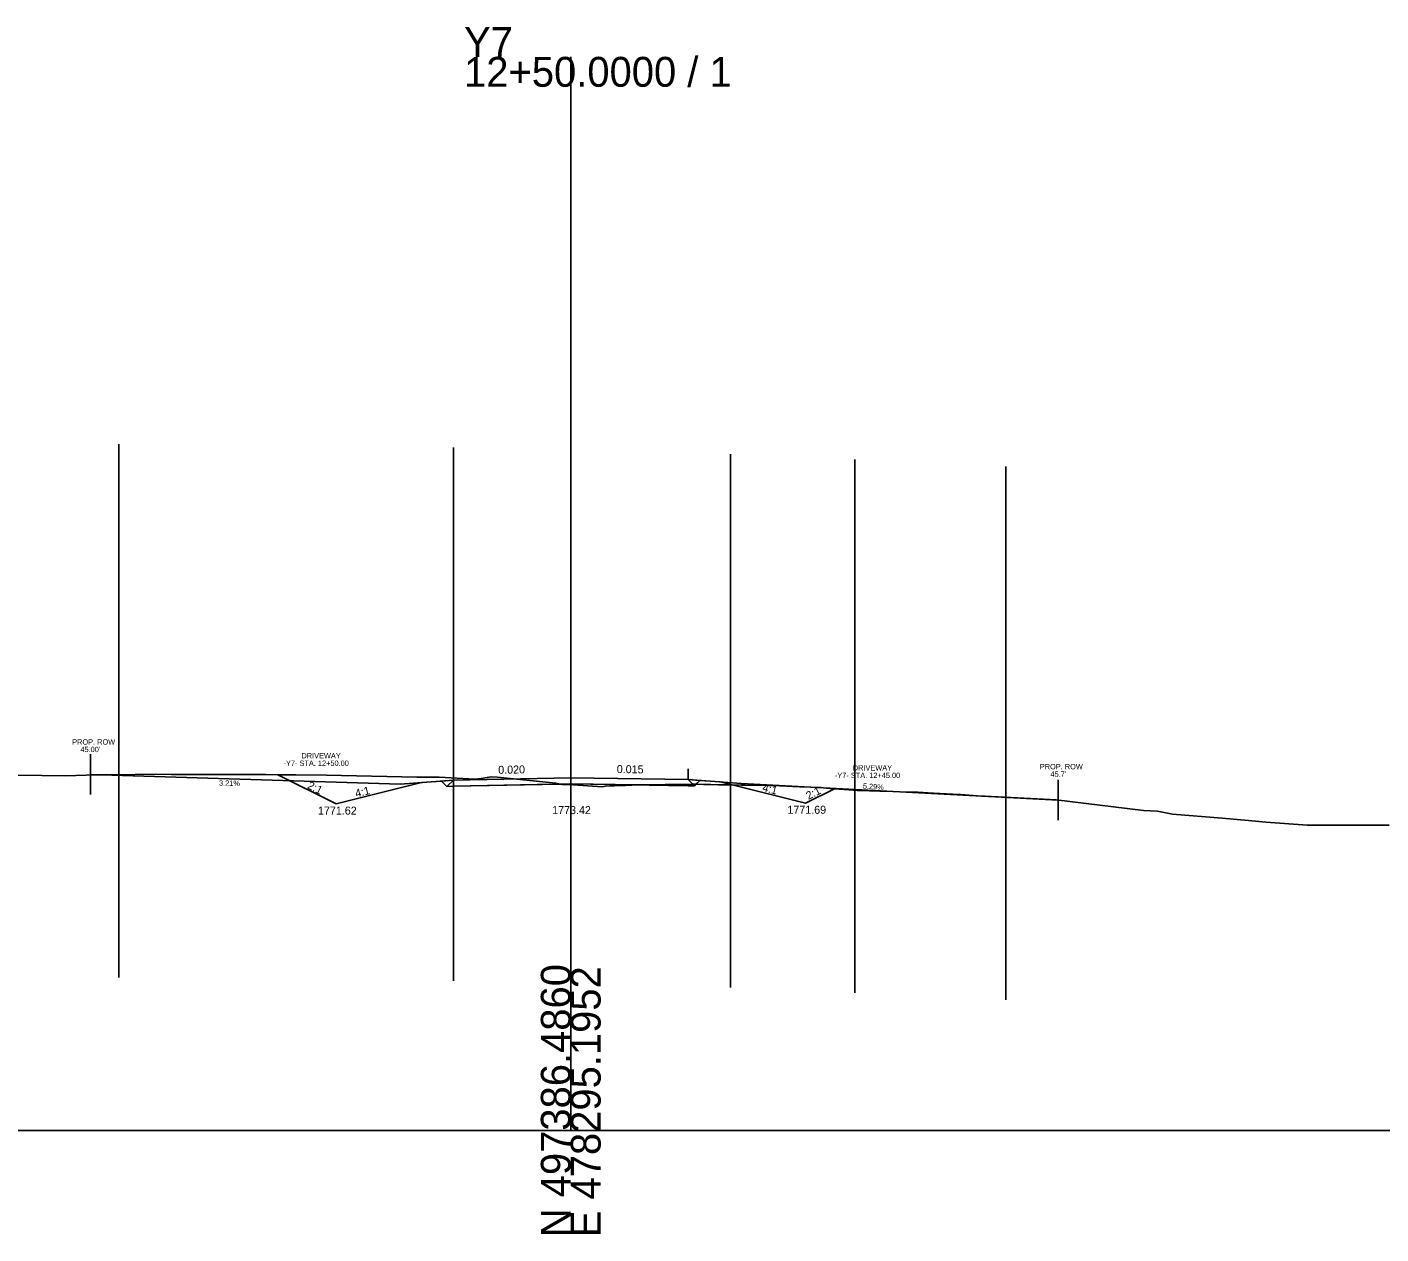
# Model space of a CAD drawing. Extents: x -26 to 403, y -10 to 4071.
# Drawn here: x 149 to 275.9, y 2490.3 to 2603.5 of the extents above; entities that cross this region are included whole.
import ezdxf

# ---------------------------------------------------------------- set-up
doc = ezdxf.new("R2010")
doc.units = 0
for name, color, linetype in [('Exist Cross Section Cell', 7, 'Continuous'), ('Exist XS Center Line Elevation Label', 7, 'Continuous'), ('Exist XS Ground Line', 7, 'Continuous'), ('Prop Road Sect_ Boring - Header (ID Tx)', 7, 'Continuous'), ('Prop Road Sect_ Boring - Material (Outline)', 7, 'Continuous'), ('Prop XS Ditch Slope Text', 7, 'Continuous'), ('Prop XS Ditch Standard Text', 7, 'Continuous'), ('Prop XS Dump Level', 7, 'Continuous'), ('Prop XS Earthwork Shape', 7, 'Continuous'), ('Prop XS EOT Tick Mark', 7, 'Continuous'), ('Prop XS Finish Grade', 7, 'Continuous'), ('Prop XS Finish Grade Earthwork', 7, 'Continuous'), ('Prop XS Finish Grade Pavement', 7, 'Continuous'), ('Prop XS Pvmt Edge Slope', 7, 'Continuous'), ('Prop XS SE Text', 7, 'Continuous'), ('Prop XS Side Slope Text', 7, 'Continuous'), ('Prop XS Subgrade Earthwork', 7, 'Continuous'), ('Scratch_Level_2', 7, 'Continuous'), ('Scratch_Level_5', 7, 'Continuous')]:
    doc.layers.add(name, color=color, linetype=linetype)

msp = doc.modelspace()

# ---------------------------------------------------------------- linework, layer by layer
at = {"layer": 'Exist Cross Section Cell'}
for p, q in [((200, 2500), (200, 2600.66)), ((0, 2500), (200, 2500)), ((200, 2500), (400, 2500))]:
    msp.add_line(p, q, dxfattribs=at)
at = {"layer": 'Exist XS Ground Line'}
msp.add_lwpolyline([(132.59, 2533.55), (152.64, 2533.26), (155.54, 2533.36), (157.27, 2533.34), (161.05, 2533.41), (162.58, 2533.39), (168.64, 2533.38), (171.39, 2533.37), (177.12, 2533.31), (185.56, 2533.13), (187.66, 2533.12), (191, 2532.93), (191.6, 2533), (192.53, 2533.16), (193.1, 2533.14), (198.59, 2532.56), (199.2, 2532.44), (200.27, 2532.41), (202.94, 2532.21), (203.25, 2532.29), (204.08, 2532.32), (205.1, 2532.34), (206.36, 2532.41), (207.76, 2532.42), (208.86, 2532.45), (210.56, 2532.45), (211.37, 2532.46), (212.45, 2532.45), (213.14, 2532.43), (213.84, 2532.42), (216, 2532.39), (216.39, 2532.39), (218.41, 2532.36), (218.97, 2532.34), (221.43, 2532.23), (223.48, 2532.16), (223.93, 2532.1), (224.29, 2532.08), (226.06, 2531.95), (226.85, 2531.89), (227.99, 2531.86), (228.97, 2531.83), (230.19, 2531.78), (231.49, 2531.74), (232.54, 2531.71), (234.01, 2531.64), (235.81, 2531.54), (236.52, 2531.51), (238.51, 2531.36), (238.85, 2531.34), (244.3, 2531.07), (245.51, 2530.99), (253.68, 2530.01), (254.99, 2529.93), (256.4, 2529.67), (261.05, 2529.29), (263.54, 2529.06), (265.15, 2528.91), (269.07, 2528.62), (276.72, 2528.62)], dxfattribs=at)
at = {"layer": 'Prop Road Sect_ Boring - Header (ID Tx)'}
for points in [[(211.59, 2532.32), (212.1, 2532.83), (211, 2532.91)], [(189, 2532.86), (187.9, 2532.77), (188.4, 2532.26)]]:
    msp.add_lwpolyline(points, close=True, dxfattribs=at)
at = {"layer": 'Prop Road Sect_ Boring - Material (Outline)'}
for p, q in [((155, 2535.28), (155, 2531.5)), ((155, 2533.39), (184.01, 2532.46)), ((211, 2532.91), (215.99, 2532.54)), ((189, 2532.86), (184.01, 2532.46)), ((215.99, 2532.54), (245.7, 2530.97)), ((245.7, 2532.88), (245.7, 2529.1))]:
    msp.add_line(p, q, dxfattribs=at)
at = {"layer": 'Prop XS Dump Level'}
for p, q in [((189, 2532.86), (200, 2533.08)), ((200, 2533.08), (211, 2532.91))]:
    msp.add_line(p, q, dxfattribs=at)
at = {"layer": 'Prop XS Earthwork Shape'}
for points in [[(172.53, 2533.36), (177.12, 2533.31), (185.56, 2533.13), (187.66, 2533.12), (191, 2532.93), (191.6, 2533), (192.53, 2533.16), (193.1, 2533.14), (198.59, 2532.56), (199.01, 2532.48), (189, 2532.28), (188.4, 2532.26), (187.9, 2532.77), (186, 2532.62), (178, 2530.62)], [(200, 2532.5), (199.01, 2532.48), (199.2, 2532.44), (200.27, 2532.41), (202.94, 2532.21), (203.25, 2532.29), (204.08, 2532.32), (205.1, 2532.34), (206.27, 2532.4)], [(206.27, 2532.4), (206.36, 2532.41), (207.76, 2532.42), (208.86, 2532.45), (210.56, 2532.45), (211.37, 2532.46), (211.72, 2532.46), (211.59, 2532.32), (211, 2532.33)], [(211.72, 2532.46), (212.1, 2532.83), (214, 2532.69), (215.14, 2532.4), (213.84, 2532.42), (213.14, 2532.43), (212.45, 2532.45)], [(222, 2530.69), (224.71, 2532.05), (224.29, 2532.08), (223.93, 2532.1), (223.48, 2532.16), (221.43, 2532.23), (218.97, 2532.34), (218.41, 2532.36), (216.39, 2532.39), (216, 2532.39), (215.14, 2532.4)]]:
    msp.add_lwpolyline(points, close=True, dxfattribs=at)
at = {"layer": 'Prop XS EOT Tick Mark'}
for p, q in [((189, 2532.86), (189, 2533.86)), ((211, 2532.91), (211, 2533.91))]:
    msp.add_line(p, q, dxfattribs=at)
at = {"layer": 'Prop XS Finish Grade'}
for p, q in [((211, 2532.91), (212.1, 2532.83)), ((189, 2532.86), (187.9, 2532.77))]:
    msp.add_line(p, q, dxfattribs=at)
at = {"layer": 'Prop XS Finish Grade Earthwork'}
for p, q in [((178, 2530.62), (172.53, 2533.36)), ((186, 2532.62), (178, 2530.62)), ((187.9, 2532.77), (186, 2532.62)), ((212.1, 2532.83), (214, 2532.69)), ((214, 2532.69), (222, 2530.69)), ((222, 2530.69), (224.71, 2532.05))]:
    msp.add_line(p, q, dxfattribs=at)
at = {"layer": 'Prop XS Finish Grade Pavement'}
for p, q in [((189, 2532.86), (200, 2533.08)), ((200, 2533.08), (211, 2532.91))]:
    msp.add_line(p, q, dxfattribs=at)
at = {"layer": 'Prop XS Pvmt Edge Slope'}
for p, q in [((211, 2532.91), (211.59, 2532.32)), ((189, 2532.86), (188.4, 2532.26))]:
    msp.add_line(p, q, dxfattribs=at)
at = {"layer": 'Prop XS Subgrade Earthwork'}
for p, q in [((188.4, 2532.26), (187.9, 2532.77)), ((189, 2532.28), (188.4, 2532.26)), ((200, 2532.5), (189, 2532.28)), ((211, 2532.33), (200, 2532.5)), ((211, 2532.33), (211.59, 2532.32)), ((211.59, 2532.32), (212.1, 2532.83))]:
    msp.add_line(p, q, dxfattribs=at)
at = {"layer": 'Scratch_Level_2'}
for p, q in [((157.65, 2564.35), (157.65, 2514.35)), ((189, 2564.04), (189, 2514.04)), ((214.99, 2563.41), (214.99, 2513.41)), ((226.63, 2562.9), (226.63, 2512.9)), ((240.78, 2562.25), (240.78, 2512.25))]:
    msp.add_line(p, q, dxfattribs=at)
at = {"layer": 'Scratch_Level_5'}
msp.add_lwpolyline([(132.59, 2533.55), (152.64, 2533.26), (155.54, 2533.36), (157.27, 2533.34), (161.05, 2533.41), (162.58, 2533.39), (168.64, 2533.38), (171.39, 2533.37), (177.12, 2533.31), (185.56, 2533.13), (187.66, 2533.12), (191, 2532.93), (191.6, 2533), (192.53, 2533.16), (193.1, 2533.14), (198.59, 2532.56), (199.2, 2532.44), (200.27, 2532.41), (202.94, 2532.21), (203.25, 2532.29), (204.08, 2532.32), (205.1, 2532.34), (206.36, 2532.41), (207.76, 2532.42), (208.86, 2532.45), (210.56, 2532.45), (211.37, 2532.46), (212.45, 2532.45), (213.14, 2532.43), (213.84, 2532.42), (216, 2532.39), (216.39, 2532.39), (218.41, 2532.36), (218.97, 2532.34), (221.43, 2532.23), (223.48, 2532.16), (223.93, 2532.1), (224.29, 2532.08), (226.06, 2531.95), (226.85, 2531.89), (227.99, 2531.86), (228.97, 2531.83), (230.19, 2531.78), (231.49, 2531.74), (232.54, 2531.71), (234.01, 2531.64), (235.81, 2531.54), (236.52, 2531.51), (238.51, 2531.36), (238.85, 2531.34), (244.3, 2531.07), (245.51, 2530.99), (253.68, 2530.01), (254.99, 2529.93), (256.4, 2529.67), (261.05, 2529.29), (263.54, 2529.06), (265.15, 2528.91), (269.07, 2528.62), (276.72, 2528.62)], dxfattribs=at)

# ---------------------------------------------------------------- texts
at = {"layer": 'Exist Cross Section Cell'}
for s, p in [('Y7', (190, 2600.66)), ('12+50.0000 / 1', (190, 2597.86))]:
    msp.add_text(s, height=2.8, dxfattribs=at).set_placement(p)
for s, p in [('N 497386.4860', (200, 2490)), ('E 478295.1952', (202.8, 2490))]:
    msp.add_text(s, height=2.8, rotation=90, dxfattribs=at).set_placement(p)
at = {"layer": 'Exist XS Center Line Elevation Label'}
msp.add_text('1773.42', height=0.75, dxfattribs=at).set_placement((198.26, 2529.67))
at = {"layer": 'Prop Road Sect_ Boring - Material (Outline)'}
for s, p in [('PROP. ROW', (153.27, 2536.18)), ("45.00'", (154.04, 2535.48)), ('-Y7- STA. 12+50.00', (173.08, 2534.19)), ('DRIVEWAY', (174.76, 2534.89)), ('DRIVEWAY', (226.44, 2533.75)), ('PROP. ROW', (243.97, 2533.87)), ('-Y7- STA. 12+45.00', (224.76, 2533.05)), ("45.7'", (244.97, 2533.17))]:
    msp.add_text(s, height=0.5, dxfattribs=at).set_placement(p)
for s, rotation, p in [('3.21%', 358.7527, (167.03, 2532.34)), ('5.29%', 356.3168, (227.37, 2532.06))]:
    msp.add_text(s, height=0.5, rotation=rotation, dxfattribs=at).set_placement(p)
at = {"layer": 'Prop XS Ditch Slope Text'}
for rotation, p in [(14.0362, (179.89, 2531.22)), (345.9638, (217.91, 2531.83))]:
    msp.add_text('4:1', height=0.75, rotation=rotation, dxfattribs=at).set_placement(p)
at = {"layer": 'Prop XS Ditch Standard Text'}
for s, p in [('1771.62', (176.31, 2529.62)), ('1771.69', (220.31, 2529.7))]:
    msp.add_text(s, height=0.75, dxfattribs=at).set_placement(p)
at = {"layer": 'Prop XS Dump Level'}
for p in [(186, 2532.58), (214, 2532.65)]:
    msp.add_text('Case1', height=0.04, dxfattribs=at).set_placement(p)
at = {"layer": 'Prop XS SE Text'}
for s, rotation, p in [('0.020', 1.1458, (193.21, 2533.44)), ('0.015', 359.1406, (204.31, 2533.52))]:
    msp.add_text(s, height=0.75, rotation=rotation, dxfattribs=at).set_placement(p)
at = {"layer": 'Prop XS Side Slope Text'}
for rotation, p in [(333.4349, (175.25, 2532.12)), (26.5651, (222.28, 2530.99))]:
    msp.add_text('2:1', height=0.75, rotation=rotation, dxfattribs=at).set_placement(p)

doc.saveas('drawing.dxf')
